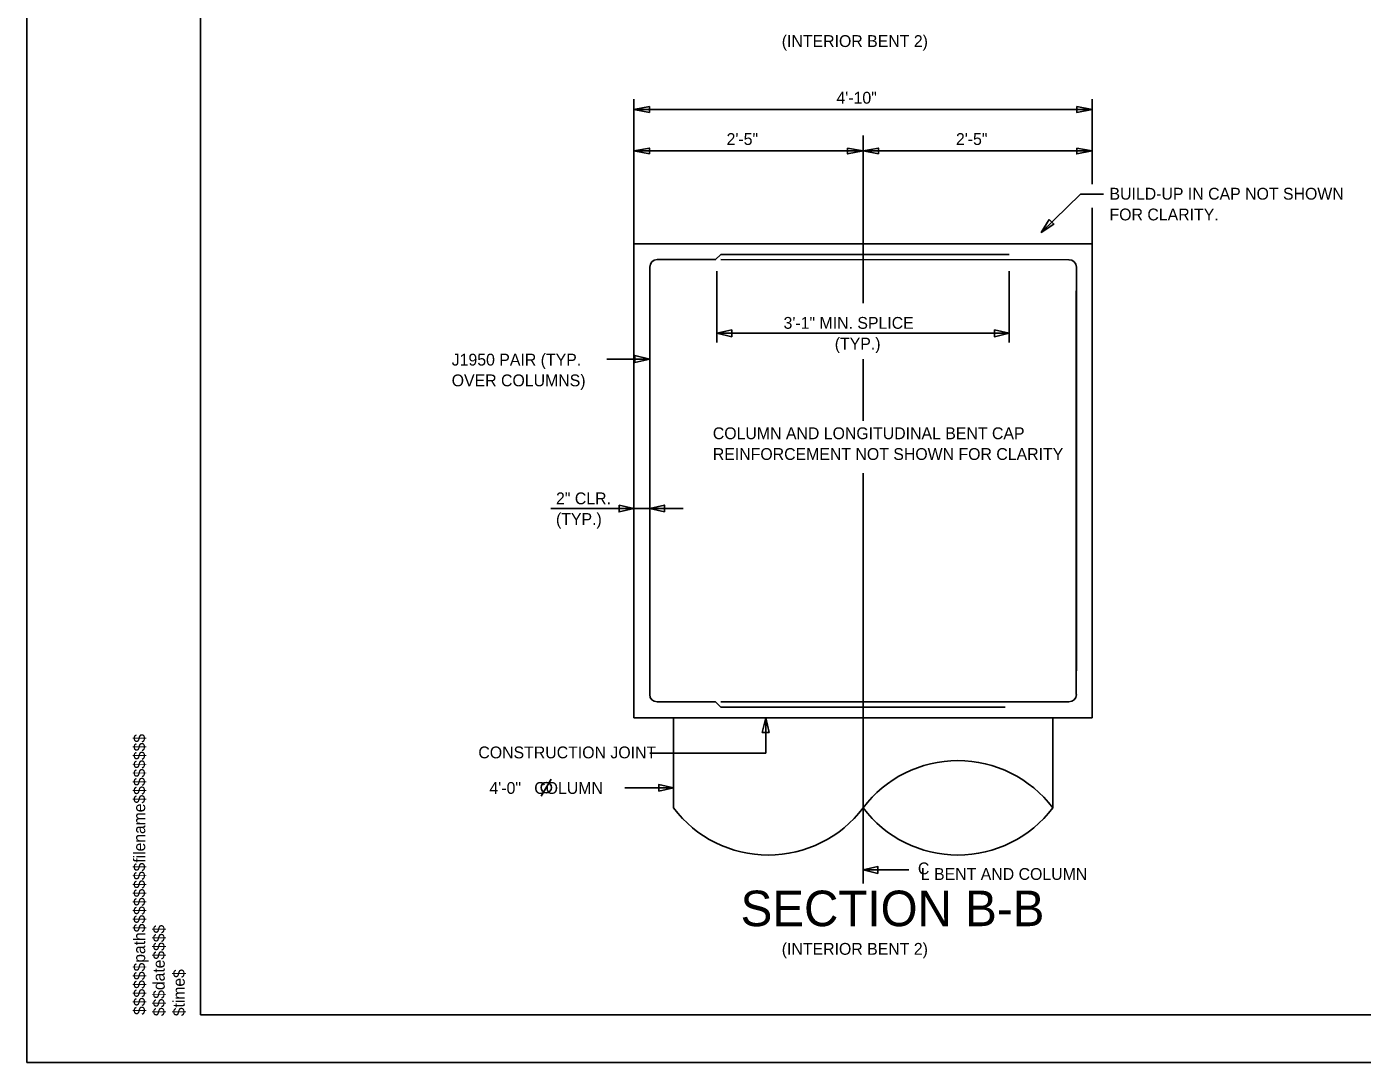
# Model space of a CAD drawing. Extents: x 1970675.2 to 1970711.3, y 796145.2 to 796167.2.
# Drawn here: x 1970675.24 to 1970689.32, y 796145.25 to 796156.18 of the extents above; entities that cross this region are included whole.
import ezdxf

# ---------------------------------------------------------------- set-up
doc = ezdxf.new("R2010")
doc.units = 0
for name, color, linetype in [('BR_AUTO DIMENSION', 7, 'Continuous'), ('BR_BORDER LINES', 7, 'Continuous'), ('BR_CENTER LINES', 7, 'Continuous'), ('BR_CONCRETE', 7, 'Continuous'), ('BR_REBAR', 7, 'Continuous'), ('BR_TEXT', 7, 'Continuous'), ('Level 31', 7, 'Continuous'), ('RD_SHT_ID', 7, 'Continuous')]:
    doc.layers.add(name, color=color, linetype=linetype)

msp = doc.modelspace()

# ---------------------------------------------------------------- linework, layer by layer
at = {"layer": 'BR_AUTO DIMENSION'}
for p, q in [((1970681.641, 796153.696), (1970681.641, 796155.409)), ((1970686.475, 796154.515), (1970686.475, 796155.409)), ((1970681.641, 796155.301), (1970686.475, 796155.301)), ((1970681.641, 796154.864), (1970684.058, 796154.864)), ((1970686.475, 796154.864), (1970684.058, 796154.864)), ((1970686.475, 796153.65), (1970686.475, 796154.264)), ((1970682.516, 796153.596), (1970682.516, 796152.842)), ((1970685.599, 796153.596), (1970685.599, 796152.842)), ((1970682.516, 796152.94), (1970685.599, 796152.94)), ((1970681.808, 796152.668), (1970681.354, 796152.668)), ((1970682.159, 796151.091), (1970680.766, 796151.091)), ((1970683.031, 796148.883), (1970683.031, 796148.51)), ((1970683.031, 796148.51), (1970681.807, 796148.51)), ((1970682.058, 796148.142), (1970681.546, 796148.142)), ((1970684.058, 796147.276), (1970684.54, 796147.276))]:
    msp.add_line(p, q, dxfattribs=at)
for points in [[(1970681.804, 796155.27), (1970681.641, 796155.301), (1970681.804, 796155.332)], [(1970686.312, 796155.332), (1970686.475, 796155.301), (1970686.312, 796155.27)], [(1970681.804, 796154.833), (1970681.641, 796154.864), (1970681.804, 796154.895)], [(1970683.895, 796154.895), (1970684.058, 796154.864), (1970683.895, 796154.833)], [(1970684.22, 796154.833), (1970684.058, 796154.864), (1970684.22, 796154.895)], [(1970686.312, 796154.895), (1970686.475, 796154.864), (1970686.312, 796154.833)], [(1970686.019, 796154.141), (1970685.937, 796154.004), (1970686.071, 796154.092)], [(1970682.672, 796152.904), (1970682.516, 796152.94), (1970682.672, 796152.976)], [(1970685.443, 796152.976), (1970685.599, 796152.94), (1970685.443, 796152.904)], [(1970681.652, 796152.704), (1970681.808, 796152.668), (1970681.652, 796152.632)], [(1970681.485, 796151.127), (1970681.641, 796151.091), (1970681.485, 796151.055)], [(1970681.963, 796151.055), (1970681.807, 796151.091), (1970681.963, 796151.127)], [(1970682.995, 796148.727), (1970683.031, 796148.883), (1970683.067, 796148.727)], [(1970681.902, 796148.106), (1970682.058, 796148.142), (1970681.902, 796148.178)], [(1970684.214, 796147.24), (1970684.058, 796147.276), (1970684.214, 796147.312)]]:
    msp.add_lwpolyline(points, close=True, dxfattribs=at)
msp.add_lwpolyline([(1970685.937, 796154.004), (1970686.351, 796154.408), (1970686.595, 796154.408)], dxfattribs=at)
at = {"layer": 'BR_BORDER LINES'}
for q in [(1970677.07, 796166.746), (1970710.736, 796145.746)]:
    msp.add_line((1970677.07, 796145.746), q, dxfattribs=at)
at = {"layer": 'BR_CENTER LINES'}
for p, q in [((1970684.058, 796155.026), (1970684.058, 796153.259)), ((1970684.058, 796152.665), (1970684.058, 796152.017)), ((1970684.058, 796151.462), (1970684.058, 796147.135))]:
    msp.add_line(p, q, dxfattribs=at)
at = {"layer": 'BR_CONCRETE'}
for p, q in [((1970681.641, 796153.883), (1970681.641, 796149.05)), ((1970681.641, 796148.883), (1970681.641, 796153.883)), ((1970686.474, 796153.883), (1970681.641, 796153.883)), ((1970686.474, 796153.883), (1970686.474, 796148.883)), ((1970681.64, 796148.883), (1970682.058, 796148.883)), ((1970682.058, 796148.883), (1970686.058, 796148.883)), ((1970682.058, 796148.883), (1970682.058, 796147.932)), ((1970686.058, 796148.883), (1970686.474, 796148.883)), ((1970686.058, 796148.883), (1970686.058, 796147.932))]:
    msp.add_line(p, q, dxfattribs=at)
for centre, start, end in [((1970685.058, 796147.178), 37.0023, 142.9977), ((1970683.058, 796148.685), 217.0023, 322.9977), ((1970685.058, 796148.685), 217.0023, 322.9977)]:
    msp.add_arc(centre, 1.252, start, end, dxfattribs=at)
at = {"layer": 'BR_REBAR'}
for p, q in [((1970682.502, 796153.717), (1970682.558, 796153.772)), ((1970685.599, 796153.772), (1970682.558, 796153.772)), ((1970681.808, 796153.639), (1970681.807, 796149.128)), ((1970681.886, 796153.717), (1970682.503, 796153.717)), ((1970686.229, 796153.716), (1970682.558, 796153.717)), ((1970686.308, 796153.638), (1970686.308, 796149.378)), ((1970686.307, 796153.388), (1970686.307, 796149.128)), ((1970682.502, 796149.049), (1970681.885, 796149.05)), ((1970682.501, 796149.05), (1970682.557, 796148.994)), ((1970686.229, 796149.049), (1970682.557, 796149.05)), ((1970685.557, 796148.994), (1970682.557, 796148.994))]:
    msp.add_line(p, q, dxfattribs=at)
for centre, start, end in [((1970681.886, 796153.639), 90, 180), ((1970686.23, 796153.638), 360, 90), ((1970681.885, 796149.128), 180, 270), ((1970686.229, 796149.128), 270, 360)]:
    msp.add_arc(centre, 0.0781, start, end, dxfattribs=at)
at = {"layer": 'BR_TEXT'}
for p, q in [((1970682.558, 796152.94), (1970682.635, 796152.94)), ((1970685.599, 796152.94), (1970685.502, 796152.94)), ((1970680.664, 796148.054), (1970680.769, 796148.236))]:
    msp.add_line(p, q, dxfattribs=at)
msp.add_circle((1970680.716, 796148.145), 0.055, dxfattribs=at)
at = {"layer": 'Level 31'}
msp.add_lwpolyline([(1970675.236, 796145.246), (1970711.236, 796145.246), (1970711.236, 796167.246), (1970675.236, 796167.246)], close=True, dxfattribs=at)

# ---------------------------------------------------------------- texts
at = {"layer": 'BR_AUTO DIMENSION'}
for s, p in [('4\'-10"', (1970683.777, 796155.363)), ('2\'-5"', (1970682.618, 796154.927)), ('2\'-5"', (1970685.037, 796154.927))]:
    msp.add_text(s, height=0.125, dxfattribs=at).set_placement(p)
at = {"layer": 'BR_TEXT'}
for s, p in [('(INTERIOR BENT 2)', (1970683.2, 796155.961)), ('BUILD-UP IN CAP NOT SHOWN', (1970686.657, 796154.35)), ('FOR CLARITY.', (1970686.657, 796154.131)), ('3\'-1" MIN. SPLICE', (1970683.219, 796152.987)), ('(TYP.)', (1970683.759, 796152.768)), ('J1950 PAIR (TYP.', (1970679.719, 796152.599)), ('OVER COLUMNS)', (1970679.719, 796152.38)), ('COLUMN AND LONGITUDINAL BENT CAP', (1970682.473, 796151.822)), ('REINFORCEMENT NOT SHOWN FOR CLARITY', (1970682.473, 796151.603)), ('2" CLR.', (1970680.819, 796151.135)), ('(TYP.)', (1970680.819, 796150.917)), ('CONSTRUCTION JOINT', (1970680, 796148.454)), ('4\'-0"   COLUMN', (1970680.117, 796148.079)), ('C', (1970684.636, 796147.23)), ('L BENT AND COLUMN', (1970684.667, 796147.171)), ('(INTERIOR BENT 2)', (1970683.2, 796146.381))]:
    msp.add_text(s, height=0.125, rotation=360, dxfattribs=at).set_placement(p)
msp.add_text('SECTION B-B', height=0.375, dxfattribs=at).set_placement((1970682.766, 796146.683))
at = {"layer": 'RD_SHT_ID'}
for s, height, p in [('$$$$$$path$$$$$$$$filename$$$$$$$$', 0.12347, (1970676.486, 796145.746)), ('$$$date$$$$', 0.12347, (1970676.692, 796145.733)), ('$time$', 0.1235, (1970676.903, 796145.733))]:
    msp.add_text(s, height=height, rotation=90, dxfattribs=at).set_placement(p)

doc.saveas('drawing.dxf')
